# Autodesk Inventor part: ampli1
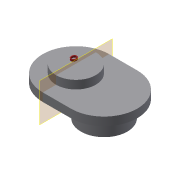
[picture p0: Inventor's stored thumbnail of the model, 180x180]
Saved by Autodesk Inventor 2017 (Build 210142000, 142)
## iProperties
Created: 2009-06
Part Number: ampli1
Document SubType Name: Modeling
Designer: ajtco
Manufacturer: Standard
Standards Organization: Custom
Material: Générique
Density: 1 g/cm^3
Appearance: Par défaut
Author: ajtco
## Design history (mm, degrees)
sketch "Esquisse1"
  geometry: L1 (-0.276, 19.998)-(16.998, 20); L2 (0.002, -20)-(17.276, -19.998); A1 r 20 centre (0, 0) between (0.271, 19.998) and (0.002, -20); A2 r 20 centre (17, 0) between (16.729, -19.998) and (16.998, 20)
  constraints: 6 point on circle, 4 end point, 2 centre point, 2 point on line, 2 tangent, 1 parallel
  dimensions: "d0" = 40 diameter of A1; "d1" = 40 diameter of A2; "d2" = 17 distance of A2.centre A1.centre
extrude "Extrusion1" new body sketch "Esquisse1" distance "d3" = 5; taper "d4" = 0 deg
sketch "Esquisse2"
  geometry: C1 r 12 at (0, 0); A1 r 20 centre (0, 0) between (-0.276, 19.998) and (0.002, -20) reference
  constraints: 1 centre point, 1 coincident
  dimensions: "d5" = 24 diameter of C1
extrude "Extrusion2" join sketch "Esquisse2" distance "d6" = 5; taper "d7" = 0 deg
sketch "Esquisse3"
  geometry: C1 r 14 at (-17, 0); A1 r 20 centre (-17, 0) between (-16.998, 20) and (-17.276, -19.998) reference
  constraints: 1 centre point, 1 coincident
  dimensions: "d8" = 28 diameter of C1
extrude "Extrusion3" join sketch "Esquisse3" distance "d9" = 10; taper "d10" = 0 deg
sketch "Esquisse4"
  geometry: L1 (-4.602, 3.485)-(-1.196, 3.485); L2 (-1.196, 3.485)-(-1.196, -0.163); L3 (-1.196, -0.163)-(-4.602, -0.163); L4 (-4.602, -0.163)-(-4.602, 3.485); 1 further point
  constraints: 2 other
feature "Gravure1" sketch "Esquisse4" dims "d0" = 40, "d1" = 40, "d2" = 17, "d11" = 1, "d12" = 0
node "Solide1"
node "Corps solides"
node "Corps surfaciques"
